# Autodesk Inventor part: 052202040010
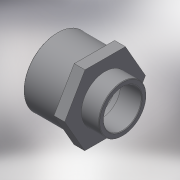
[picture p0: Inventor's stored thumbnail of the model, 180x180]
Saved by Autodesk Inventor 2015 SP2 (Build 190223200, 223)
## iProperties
Created: 2017-10
Part Number: 052202040010
Material: Generic
Description: PLASSON BUSHING ADAP. THR-CE 40(50)-1"
Document SubType Name: Modeling
Designer: KIM
Density: 1 g/cm^3
Appearance: Default
Author: KIM
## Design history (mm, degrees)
derived "052202.ipt"
feature "Solid1::052202.ipt"
tag "TaggingFeature1"
body "Solid1"
other parameters: "d0" = 66, "d13" = 0, "d14" = 0.4, "d17" = 31, "d18" = 22.8, "d21" = 33.249, "d22" = 26, "d23" = 38, "d24" = 26.5992, "d25" = 19, "d26" = -31, "R_" = 33.249, "B_" = 12, "L_" = 31, "lt_" = 19, "H_" = 66, "l_" = 26
